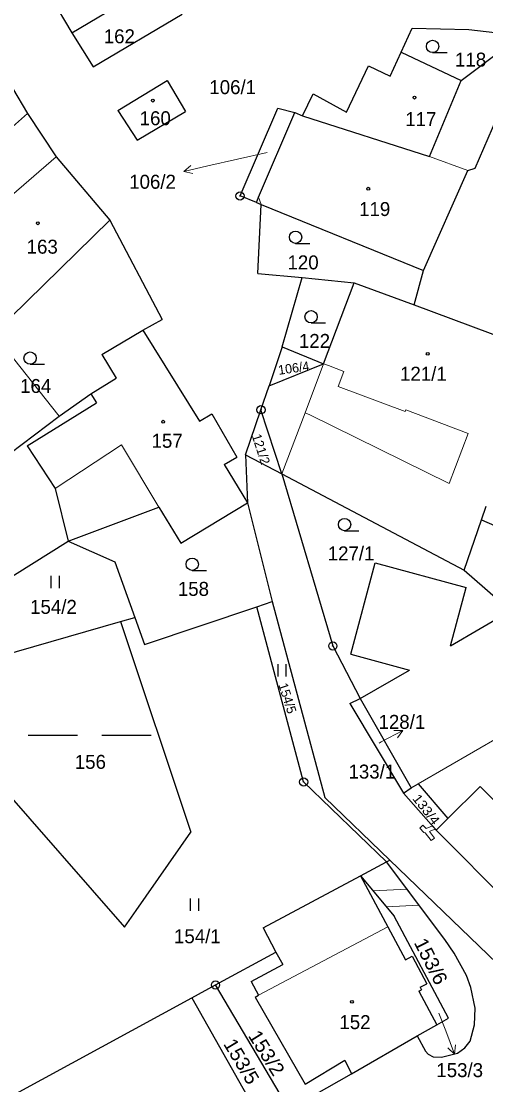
# Model space of a CAD drawing. Extents: x -633485 to -630509, y -1112692 to -1108818.
# Drawn here: x -631887.2 to -631830.6, y -1111847.5 to -1111718.1 of the extents above; entities that cross this region are included whole.
import ezdxf
from ezdxf.enums import TextEntityAlignment as Align

# ---------------------------------------------------------------- set-up
doc = ezdxf.new("R2010")
doc.units = 0
doc.header["$LTSCALE"] = 0.68
for name, color, linetype, lineweight in [('1', 7, 'Continuous', 25), ('13', 7, 'Continuous', 13), ('3', 7, 'Continuous', 25), ('4', 7, 'Continuous', 13), ('5', 7, 'Continuous', 25), ('7', 7, 'Continuous', 13), ('8', 7, 'Continuous', 25)]:
    doc.layers.add(name, color=color, linetype=linetype, lineweight=lineweight)
doc.layers.add('2', color=7, linetype='Continuous')

msp = doc.modelspace()

# ---------------------------------------------------------------- linework, layer by layer
at = {"layer": '1'}
for p, q in [((-631885.14, -1111712.49), (-631881.01, -1111719.45)), ((-631881.01, -1111719.45), (-631870.08, -1111712.97)), ((-631878.44, -1111723.62), (-631867.59, -1111717.18)), ((-631892.89, -1111718.42), (-631886.41, -1111729.28)), ((-631881.01, -1111719.45), (-631878.44, -1111723.62)), ((-631840.91, -1111721.81), (-631839.56, -1111718.9)), ((-631839.56, -1111718.9), (-631832.68, -1111719.04)), ((-631832.68, -1111719.04), (-631828.44, -1111719.54)), ((-631831.89, -1111735.93), (-631825.35, -1111720.7)), ((-631842.26, -1111724.74), (-631840.91, -1111721.81)), ((-631840.91, -1111721.81), (-631833.63, -1111725.28)), ((-631833.63, -1111725.28), (-631828.85, -1111721.71)), ((-631847.58, -1111729.1), (-631844.9, -1111723.48)), ((-631844.9, -1111723.48), (-631842.26, -1111724.74)), ((-631875.42, -1111728.9), (-631869.42, -1111725.27)), ((-631869.42, -1111725.27), (-631867.19, -1111729.04)), ((-631837.48, -1111734.5), (-631833.63, -1111725.28)), ((-631852.92, -1111729.56), (-631851.64, -1111726.9)), ((-631851.64, -1111726.9), (-631847.58, -1111729.1)), ((-631855.95, -1111728.61), (-631853.87, -1111729.16)), ((-631896.52, -1111738.17), (-631886.41, -1111729.28)), ((-631886.41, -1111729.28), (-631882.93, -1111734.57)), ((-631875.42, -1111728.9), (-631873.05, -1111732.54)), ((-631873.05, -1111732.54), (-631867.19, -1111729.04)), ((-631858.27, -1111739.47), (-631853.87, -1111729.16)), ((-631853.87, -1111729.16), (-631852.92, -1111729.56)), ((-631852.92, -1111729.56), (-631837.48, -1111734.5)), ((-631882.93, -1111734.57), (-631876.4, -1111742.27)), ((-631838.2, -1111748.4), (-631832.78, -1111736.22)), ((-631832.78, -1111736.22), (-631831.89, -1111735.93)), ((-631858.54, -1111740.12), (-631858.27, -1111739.47)), ((-631858.54, -1111740.12), (-631857.97, -1111740.36)), ((-631858.38, -1111748.75), (-631857.97, -1111740.36)), ((-631857.97, -1111740.36), (-631838.2, -1111748.4)), ((-631888.48, -1111754.09), (-631876.4, -1111742.27)), ((-631876.4, -1111742.27), (-631870.01, -1111754.36)), ((-631858.38, -1111748.75), (-631852.96, -1111749.25)), ((-631855.4, -1111757.69), (-631852.96, -1111749.25)), ((-631852.96, -1111749.25), (-631846.62, -1111749.87)), ((-631839.35, -1111752.55), (-631838.2, -1111748.4)), ((-631850.36, -1111759.73), (-631846.62, -1111749.87)), ((-631846.62, -1111749.87), (-631839.35, -1111752.55)), ((-631839.35, -1111752.55), (-631824.16, -1111758.2)), ((-631872.38, -1111755.63), (-631870.01, -1111754.36)), ((-631877.38, -1111758.62), (-631872.38, -1111755.63)), ((-631872.38, -1111755.63), (-631865.48, -1111766.72)), ((-631855.4, -1111757.69), (-631857, -1111762.41)), ((-631855.4, -1111757.69), (-631850.36, -1111759.73)), ((-631877.38, -1111758.62), (-631875.61, -1111761.5)), ((-631857, -1111762.41), (-631850.36, -1111759.73)), ((-631878.7, -1111763.37), (-631875.61, -1111761.5)), ((-631882.56, -1111766.1), (-631878.7, -1111763.37)), ((-631878.7, -1111763.37), (-631878.02, -1111764.48)), ((-631857.99, -1111765.33), (-631857, -1111762.41)), ((-631886.44, -1111769.72), (-631878.02, -1111764.48)), ((-631898.71, -1111778.33), (-631882.56, -1111766.1)), ((-631865.48, -1111766.72), (-631863.96, -1111765.81)), ((-631863.96, -1111765.81), (-631860.93, -1111771.09)), ((-631859.86, -1111770.82), (-631857.99, -1111765.33)), ((-631855.43, -1111773.12), (-631857.99, -1111765.33)), ((-631886.44, -1111769.72), (-631883.06, -1111774.91)), ((-631862.47, -1111771.98), (-631860.93, -1111771.09)), ((-631859.86, -1111770.82), (-631855.43, -1111773.12)), ((-631859.86, -1111770.82), (-631859.64, -1111776.66)), ((-631862.47, -1111771.98), (-631859.64, -1111776.66)), ((-631855.43, -1111773.12), (-631833.23, -1111784.83)), ((-631855.43, -1111773.12), (-631849.24, -1111794.07)), ((-631883.06, -1111774.91), (-631881.46, -1111781.3)), ((-631881.46, -1111781.3), (-631870.41, -1111777.2)), ((-631870.41, -1111777.2), (-631867.73, -1111781.57)), ((-631867.73, -1111781.57), (-631859.64, -1111776.66)), ((-631859.64, -1111776.66), (-631856.61, -1111788.65)), ((-631831.15, -1111778.74), (-631830.57, -1111777.04)), ((-631833.23, -1111784.83), (-631831.15, -1111778.74)), ((-631831.15, -1111778.74), (-631809.24, -1111788.21)), ((-631892.26, -1111788.08), (-631881.46, -1111781.3)), ((-631881.46, -1111781.3), (-631875.79, -1111783.82)), ((-631875.79, -1111783.82), (-631873.36, -1111790.6)), ((-631847.06, -1111795.06), (-631844.1, -1111783.97)), ((-631844.1, -1111783.97), (-631832.99, -1111786.94)), ((-631833.23, -1111784.83), (-631827.9, -1111789.52)), ((-631834.92, -1111794.04), (-631832.99, -1111786.94)), ((-631834.92, -1111794.04), (-631824.7, -1111788.1)), ((-631872.18, -1111793.89), (-631858.5, -1111789.29)), ((-631858.5, -1111789.29), (-631856.61, -1111788.65)), ((-631852.79, -1111810.62), (-631858.5, -1111789.29)), ((-631875.1, -1111791.1), (-631873.36, -1111790.6)), ((-631873.36, -1111790.6), (-631872.18, -1111793.89)), ((-631889.92, -1111795.35), (-631875.1, -1111791.1)), ((-631875.1, -1111791.1), (-631866.54, -1111816.71)), ((-631849.24, -1111794.07), (-631845.89, -1111800.46)), ((-631847.06, -1111795.06), (-631839.9, -1111797.02)), ((-631845.89, -1111800.46), (-631839.9, -1111797.02)), ((-631847.17, -1111801.07), (-631845.89, -1111800.46)), ((-631847.17, -1111801.07), (-631840.63, -1111812)), ((-631845.89, -1111800.46), (-631839.7, -1111811.34)), ((-631890.13, -1111810.57), (-631874.62, -1111828.29)), ((-631842.69, -1111820.35), (-631852.79, -1111810.62)), ((-631840.63, -1111812), (-631839.7, -1111811.34)), ((-631839.7, -1111811.34), (-631838.83, -1111810.84)), ((-631838.83, -1111810.84), (-631835.23, -1111815.07)), ((-631836.65, -1111816.48), (-631840.63, -1111812)), ((-631836.65, -1111816.48), (-631835.23, -1111815.07)), ((-631836.65, -1111816.48), (-631823.73, -1111829.48)), ((-631873.19, -1111826.24), (-631866.54, -1111816.71)), ((-631845.85, -1111822.03), (-631842.69, -1111820.35)), ((-631842.69, -1111820.35), (-631842.28, -1111820.13)), ((-631842.28, -1111820.13), (-631829.28, -1111832.66)), ((-631857.73, -1111828.37), (-631845.85, -1111822.03)), ((-631845.85, -1111822.03), (-631842.53, -1111828.24)), ((-631845.85, -1111822.03), (-631841.78, -1111826.93)), ((-631874.62, -1111828.29), (-631873.19, -1111826.24)), ((-631857.73, -1111828.37), (-631856.16, -1111831.31)), ((-631863.52, -1111835.32), (-631856.16, -1111831.31)), ((-631856.16, -1111831.31), (-631855.34, -1111832.83)), ((-631839.59, -1111831.82), (-631837.8, -1111835.17)), ((-631859.2, -1111834.89), (-631855.34, -1111832.83)), ((-631866.42, -1111836.9), (-631863.52, -1111835.32)), ((-631854.56, -1111850.42), (-631863.52, -1111835.32)), ((-631859.2, -1111834.89), (-631858.29, -1111836.58)), ((-631838.75, -1111836.07), (-631838.44, -1111835.9)), ((-631838.75, -1111836.07), (-631836.57, -1111840.16)), ((-631838.6, -1111835.6), (-631837.8, -1111835.17)), ((-631838.6, -1111835.6), (-631838.44, -1111835.9)), ((-631888.32, -1111848.82), (-631866.42, -1111836.9)), ((-631866.42, -1111836.9), (-631857.68, -1111852.27)), ((-631858.68, -1111836.79), (-631858.29, -1111836.58)), ((-631858.68, -1111836.79), (-631852.6, -1111847.41)), ((-631838.96, -1111841.53), (-631836.57, -1111840.16)), ((-631846.97, -1111846.13), (-631838.96, -1111841.53)), ((-631852.6, -1111847.41), (-631847.77, -1111844.48)), ((-631847.77, -1111844.48), (-631846.97, -1111846.13)), ((-631854.56, -1111850.42), (-631846.97, -1111846.13))]:
    msp.add_line(p, q, dxfattribs=at)
for points in [[(-631858.54, -1111740.12), (-631860.54, -1111739.31), (-631855.95, -1111728.61)], [(-631856.61, -1111788.65), (-631850.21, -1111812.49), (-631842.28, -1111820.13)], [(-631838.96, -1111841.53), (-631837.96, -1111843.37), (-631837.62, -1111843.73), (-631837.03, -1111844.06), (-631835.99, -1111844.12), (-631834.04, -1111843.6), (-631833.15, -1111842.96), (-631832.53, -1111842.16), (-631831.99, -1111840.16), (-631831.9, -1111838.13), (-631832.45, -1111835.62), (-631832.97, -1111834.16), (-631834.45, -1111831.45), (-631835.61, -1111829.78), (-631842.69, -1111820.35)], [(-631836.57, -1111840.16), (-631835.16, -1111839.35), (-631841.78, -1111826.93)], [(-631842.53, -1111828.24), (-631840.39, -1111832.25), (-631839.59, -1111831.82)]]:
    msp.add_lwpolyline(points, dxfattribs=at)
at = {"layer": '13'}
for points in [[(-631882.56, -1111766.1), (-631878.7, -1111763.37), (-631875.61, -1111761.5), (-631877.38, -1111758.62), (-631872.38, -1111755.63), (-631870.01, -1111754.36), (-631876.4, -1111742.27), (-631888.48, -1111754.09), (-631895.25, -1111747.35), (-631897.14, -1111748.57), (-631890.47, -1111756.17)], [(-631838.29, -1111815.89), (-631838.65, -1111816.23), (-631838.14, -1111816.78), (-631837.98, -1111816.8), (-631837.27, -1111817.76), (-631836.87, -1111817.46), (-631837.47, -1111816.65), (-631837.22, -1111816.52), (-631836.84, -1111816.42), (-631836.71, -1111816.41), (-631837.1, -1111815.97), (-631837.4, -1111816.06), (-631837.89, -1111816.3)], [(-631844.31, -1111823.88), (-631842.72, -1111825.8), (-631838.75, -1111825.6), (-631840.2, -1111823.67)]]:
    msp.add_lwpolyline(points, close=True, dxfattribs=at)
at = {"layer": '3'}
for p, q in [((-631837.083, -1111721.86), (-631835.333, -1111721.86)), ((-631853.783, -1111745.08), (-631852.033, -1111745.08)), ((-631851.893, -1111754.77), (-631850.143, -1111754.77)), ((-631886.103, -1111759.79), (-631884.353, -1111759.79)), ((-631847.813, -1111780.05), (-631846.063, -1111780.05)), ((-631883.521, -1111787.05), (-631883.521, -1111785.55)), ((-631882.52, -1111787.05), (-631882.52, -1111785.55)), ((-631866.363, -1111784.88), (-631864.613, -1111784.88)), ((-631855.911, -1111797.78), (-631855.911, -1111796.28)), ((-631854.91, -1111797.78), (-631854.91, -1111796.28)), ((-631886.349, -1111804.93), (-631880.349, -1111804.93)), ((-631877.349, -1111804.93), (-631871.349, -1111804.93)), ((-631866.571, -1111826.31), (-631866.571, -1111824.81)), ((-631865.57, -1111826.31), (-631865.57, -1111824.81))]:
    msp.add_line(p, q, dxfattribs=at)
for centre in [(-631837.0829, -1111721.1098), (-631853.7829, -1111744.3298), (-631851.8929, -1111754.0198), (-631886.1029, -1111759.0398), (-631847.8129, -1111779.2998), (-631866.3629, -1111784.1298)]:
    msp.add_circle(centre, 0.75, dxfattribs=at)
at = {"layer": '4'}
for p, q in [((-631888.96, -1111739.77), (-631882.93, -1111734.57)), ((-631837.48, -1111734.5), (-631832.78, -1111736.22)), ((-631858.27, -1111739.47), (-631857.97, -1111740.36)), ((-631852.62, -1111765.7), (-631850.36, -1111759.73)), ((-631850.36, -1111759.73), (-631849.76, -1111759.95)), ((-631849.76, -1111759.95), (-631847.89, -1111760.66)), ((-631848.58, -1111762.48), (-631847.89, -1111760.66)), ((-631848.58, -1111762.48), (-631840.45, -1111765.56)), ((-631855.43, -1111773.12), (-631852.62, -1111765.7)), ((-631852.62, -1111765.7), (-631852.02, -1111765.93)), ((-631852.02, -1111765.93), (-631835.08, -1111774.3)), ((-631840.45, -1111765.56), (-631840.36, -1111765.32)), ((-631840.36, -1111765.32), (-631832.77, -1111768.2)), ((-631835.08, -1111774.3), (-631832.77, -1111768.2)), ((-631883.06, -1111774.91), (-631874.97, -1111769.6)), ((-631874.97, -1111769.6), (-631870.41, -1111777.2)), ((-631838.83, -1111810.84), (-631828.73, -1111805)), ((-631835.23, -1111815.07), (-631831.3, -1111811.18)), ((-631831.3, -1111811.18), (-631828.18, -1111814.3)), ((-631858.29, -1111836.58), (-631842.53, -1111828.24))]:
    msp.add_line(p, q, dxfattribs=at)
at = {"layer": '5'}
for centre in [(-631839.2968, -1111727.3392), (-631871.1568, -1111727.7092), (-631844.9268, -1111738.4292), (-631885.1668, -1111742.6392), (-631837.6868, -1111758.5192), (-631869.8968, -1111766.7892), (-631846.9068, -1111837.3792)]:
    msp.add_circle(centre, 0.175, dxfattribs=at)
at = {"layer": '7'}
for p, q in [((-631867.374, -1111736.325), (-631866.286, -1111736.588)), ((-631840.71, -1111804.341), (-631841.83, -1111804.369)), ((-631834.405, -1111843.722), (-631834.296, -1111842.607))]:
    msp.add_line(p, q, dxfattribs=at)
for points in [[(-631857.24, -1111734.04), (-631864.45, -1111735.65), (-631867.374, -1111736.325), (-631866.511, -1111735.612)], [(-631843.6, -1111805.89), (-631843.36, -1111805.75), (-631840.71, -1111804.341), (-631841.359, -1111805.253)], [(-631836.33, -1111838.74), (-631835.48, -1111840.92), (-631834.405, -1111843.722), (-631835.231, -1111842.966)]]:
    msp.add_lwpolyline(points, dxfattribs=at)
at = {"layer": '8'}
for centre, radius in [((-631860.54, -1111739.3099), 0.5), ((-631860.54, -1111739.3099), 0.0303), ((-631857.99, -1111765.3299), 0.5), ((-631857.99, -1111765.3299), 0.0303), ((-631849.24, -1111794.0699), 0.5), ((-631849.24, -1111794.0699), 0.0303), ((-631852.79, -1111810.6199), 0.5), ((-631852.79, -1111810.6199), 0.0303), ((-631863.52, -1111835.3199), 0.5), ((-631863.52, -1111835.3199), 0.0303)]:
    msp.add_circle(centre, radius, dxfattribs=at)

# ---------------------------------------------------------------- texts
at = {"layer": '2'}
for s, p in [('162', (-631877.13, -1111720.735)), ('118', (-631834.36, -1111723.575)), ('160', (-631872.76, -1111730.705)), ('117', (-631840.42, -1111730.815)), ('119', (-631846.04, -1111741.755)), ('163', (-631886.52, -1111746.335)), ('120', (-631854.76, -1111748.245)), ('122', (-631853.37, -1111757.805)), ('164', (-631887.32, -1111763.285)), ('157', (-631871.31, -1111769.955)), ('127/1', (-631849.86, -1111783.655)), ('158', (-631868.11, -1111787.975)), ('154/2', (-631886.1, -1111790.165)), ('156', (-631880.66, -1111809.025)), ('133/1', (-631847.33, -1111810.205)), ('154/1', (-631868.58, -1111830.245)), ('152', (-631848.44, -1111840.695))]:
    msp.add_text(s, height=1.7, dxfattribs=at).set_placement(p)
for s, p in [('106/1', (-631861.43, -1111726.922)), ('106/2', (-631871.19, -1111738.435)), ('121/1', (-631838.21, -1111761.792)), ('128/1', (-631840.83, -1111804.155)), ('153/3', (-631833.79, -1111846.535))]:
    msp.add_text(s, height=1.7, dxfattribs=at).set_placement(p, align=Align.CENTER)
for s, height, rotation, p in [('106/4', 1.139, 8, (-631853.9203, -1111760.8149)), ('121/2', 1.14, 288, (-631858.528, -1111770.2959)), ('154/5', 1.14, 288, (-631855.298, -1111800.6059))]:
    msp.add_text(s, height=height, rotation=rotation, dxfattribs=at).set_placement(p, align=Align.CENTER)
for s, height, rotation, width, p in [('133/4', 1.14, 308, 1.1, (-631838.3177, -1111814.3071)), ('153/6', 1.7, 297, 1.05, (-631838.0525, -1111832.8281)), ('153/2', 1.7, 302, 1.05, (-631858.0271, -1111844.0341)), ('153/5', 1.7, 301, 1.05, (-631861.0895, -1111845.0507))]:
    msp.add_text(s, height=height, rotation=rotation, dxfattribs=dict(at, width=width)).set_placement(p, align=Align.CENTER)

doc.saveas('drawing.dxf')
